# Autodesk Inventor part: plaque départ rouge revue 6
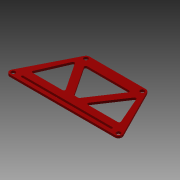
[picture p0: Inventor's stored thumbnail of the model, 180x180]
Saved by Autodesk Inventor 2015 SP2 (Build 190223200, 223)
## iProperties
Created: 2015-08
Part Number: plaque départ rouge revue 6
Material: Générique
Document SubType Name: Modeling
Designer: Dominique
Density: 1 g/cm^3
Appearance: Rouge
Author: Dominique
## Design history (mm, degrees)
sketch "Esquisse1" dims "d28" = 60
  geometry: L1 (0, -5)-(110, -5); L2 (0, 5)-(110, 5); L3 (0, 0)-(102, 0); L4 (0, 72)-(24.95, 73.58); L5 (39.034, 94.236)-(24.95, 73.58); L6 (0, 0)-(24.95, 73.58); L7 (0, 0)-(77.695, 0); L8 (0, 0)-(34.388, 69.671); L9 (39.034, 94.236)-(34.388, 69.671); L10 (-150, 5)-(0, 5); L11 (0, -5)-(-150, -5); L12 (0, 0)-(-101.627, 42.095); L13 (-150, 0)-(0, 0); L14 (99.713, 46.715)-(-1.913, 4.619); L15 (103.54, 37.476)-(1.913, -4.619); L16 (0, 0)-(0, 102); L17 (0, 102)-(0, 72); L18 (-29.83, 68.812)-(0, 0); L19 (-150, 0)-(-120.166, 68.811); L20 (-150, 0)-(-75, 0); L21 (-120.166, 68.811)-(-29.83, 68.812); C1 r 5 at (24.95, 73.58); C2 r 5 at (34.388, 69.671); C3 r 5 at (-29.83, 68.812); C4 r 5 at (-11.182, 74.162); C5 r 5 at (-120.166, 68.811); A1 r 5 centre (0, 0) between (0, -5) and (0, 5); A2 r 5 centre (110, 0) between (110, -5) and (110, 5); A3 r 5 centre (-150, 0) between (-150, 5) and (-150, -5); A4 r 5 centre (-101.627, 42.095) between (-99.609, 46.67) and (-103.435, 37.433); A5 r 5 centre (101.627, 42.095) between (99.713, 46.715) and (103.54, 37.476); A6 r 110 centre (0, 0) between (-99.609, 46.67) and (-103.435, 37.433); A7 r 150 centre (0, 0) between (-149.917, 5) and (-149.917, -5); A8 r 110 centre (0, 0) between (109.886, -5) and (109.886, 5); A9 r 110 centre (0, 0) between (103.435, 37.432) and (99.608, 46.671); A10 r 30 centre (0, 102) between (0, 72) and (-11.182, 74.162); A11 r 75 centre (0, 0) between (-29.83, 68.812) and (-11.182, 74.162); 1 further point
  constraints: 42 end point, 27 point on circle, 16 centre point, 11 tangent, 8 coincident, 6 point on line, 4 horizontal, 1 collinear, 1 equal length, 1 vertical, 3 other
  dimensions: "d0" = 10 diameter of A1; "d1" = 10 diameter of A2; "d2" = 110 distance of A2.centre point (0, 0); "d13" = 10 diameter of C1; "d14" = 71.2689 deg angle of L1 L6; "d18" = 77.69525 distance of L3.start L6.end; "d19" = 77.69525 distance of L3.start L8.end (= d18); "d20" = 10 diameter of C2; "d21" = 10 diameter of A3; "d22" = 150 distance of point (0, 0) L13.start; "d23" = 10 diameter of A4; "d25" = 22.5 deg angle of L10 L12; "d26" = 10 diameter of A5; "d27" = 102 distance of L13.end L16.end; "d29" = 150 diameter of A11; "d30" = 10 diameter of C3; "d31" = 10 diameter of C4; "d32" = 66.5633 deg angle of L13 L18; "d33" = 66.56 deg angle of L20 L19; "d34" = 10 diameter of C5; "d35" = 75 distance of L18.start L3.start; "d36" = 75 distance of L13.start L19.end (= d35)
sketch "Esquisse2"
  geometry: L1 (-34.83, 73.82)-(-75, 73.819) reference; L2 (-75, -4.993)-(0, -4.993) reference; L3 (-75, 3.007)-(-11.5, 3.007); L4 (-10, 1.507)-(-10, 1.507); L5 (-11.5, 0.007)-(-75, 0.007); L6 (-58.613, 16.278)-(-32.731, 55.178); L7 (-29.231, 54.866)-(-12.367, 15.966); L8 (-14.202, 13.17)-(-56.948, 13.17); L9 (-75, 60.227)-(-45.115, 60.227); L10 (-43.45, 57.119)-(-70.905, 15.857); L11 (-72.57, 14.965)-(-75, 14.965); L12 (0, 0.007)-(148.726, 0.007); L13 (-30.369, 71.078)-(4.461, 2.265); L14 (-77.43, 14.965)-(-75, 14.965); L15 (-140, 1.507)-(-140, 1.507); L16 (-119.631, 71.078)-(-154.461, 2.265); L17 (-120.769, 54.866)-(-137.633, 15.966); L18 (-115.17, 73.82)-(-75, 73.819); L19 (-75, -4.993)-(-150, -4.993); L20 (-75, 3.007)-(-138.5, 3.007); L21 (-138.5, 0.007)-(-75, 0.007); L22 (-135.798, 13.17)-(-93.052, 13.17); L23 (-106.55, 57.119)-(-79.095, 15.857); L24 (-91.387, 16.278)-(-117.269, 55.178); L25 (-75, 60.227)-(-104.885, 60.227); C1 r 3 at (0, 0.007); C2 r 3 at (-34.83, 68.82); C3 r 3 at (-150, 0.007); C4 r 3 at (-115.17, 68.82); A1 r 5 centre (0, 0.007) between (0, -4.993) and (4.461, 2.265); A2 r 1.5 centre (-11.5, 1.507) between (-10, 1.507) and (-11.5, 3.007); A3 r 1.5 centre (-11.5, 1.507) between (-11.5, 0.007) and (-10, 1.507); A4 r 2 centre (-72.57, 16.965) between (-72.57, 14.965) and (-70.905, 15.857); A5 r 2 centre (-45.115, 58.227) between (-43.45, 57.119) and (-45.115, 60.227); A6 r 2 centre (-31.066, 54.07) between (-29.231, 54.866) and (-32.731, 55.178); A7 r 2 centre (-56.948, 15.17) between (-58.613, 16.278) and (-56.948, 13.17); A8 r 2 centre (-14.202, 15.17) between (-14.202, 13.17) and (-12.367, 15.966); A9 r 5 centre (-34.83, 68.82) between (-30.369, 71.078) and (-34.83, 73.82); A10 r 2 centre (-93.052, 15.17) between (-93.052, 13.17) and (-91.387, 16.278); A11 r 2 centre (-77.43, 16.965) between (-79.095, 15.857) and (-77.43, 14.965); A12 r 5 centre (-150, 0.007) between (-154.461, 2.265) and (-150, -4.993); A13 r 1.5 centre (-138.5, 1.507) between (-140, 1.507) and (-138.5, 0.007); A14 r 1.5 centre (-138.5, 1.507) between (-138.5, 3.007) and (-140, 1.507); A15 r 2 centre (-135.798, 15.17) between (-137.633, 15.966) and (-135.798, 13.17); A16 r 2 centre (-104.885, 58.227) between (-104.885, 60.227) and (-106.55, 57.119); A17 r 2 centre (-118.934, 54.07) between (-117.269, 55.178) and (-120.769, 54.866); A18 r 5 centre (-115.17, 68.82) between (-115.17, 73.82) and (-119.631, 71.078); 12 further points
  constraints: 52 end point, 38 point on circle, 22 centre point, 20 point on line, 17 tangent, 5 equal radius, 4 coincident, 4 horizontal, 3 parallel, 1 perpendicular, 1 other
  dimensions: "d42" = 10 diameter of A1; "d48" = 6 diameter of C1; "d51" = 3 distance of point (-10, 3.007) point (-10, 0.007); "d53" = 10 distance from line of L4 point (0, 0); "d56" = 3 distance between parallel lines of L5 L3 (derived); "d62" = 56.3616 deg angle of L8 L6 (= d61); "d64" = 63.23263 distance from line of point (-30.693, 58.24) L2 (= d63); "d65" = 10 distance between parallel lines of L6 L10; "d75" = 6 diameter of C2
extrude "Extrusion1" new body sketch "Esquisse2" distance "d68" = 3; taper "d69" = 0 deg
node "Solide1"
other parameters: "d61" = 56.3616 deg, "d63" = 63.23263
